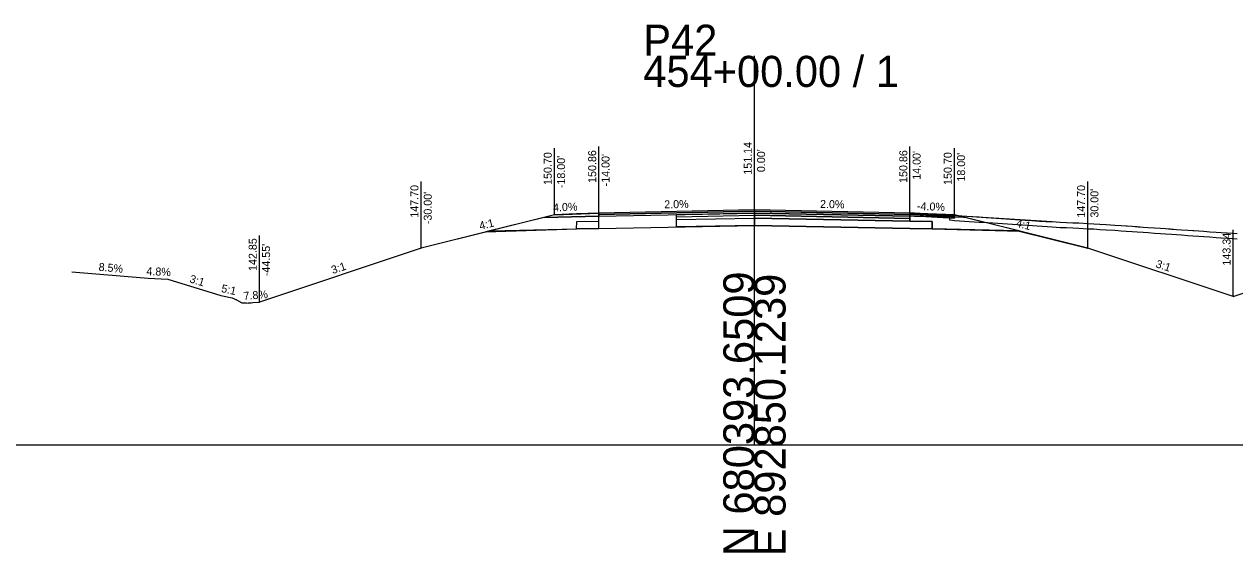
# Model space of a CAD drawing. Extents: x -26 to 4403, y -13 to 9578.
# Drawn here: x 184.3 to 293.2, y 3490.3 to 3537.8 of the extents above; entities that cross this region are included whole.
import ezdxf

# ---------------------------------------------------------------- set-up
doc = ezdxf.new("R2010")
doc.units = 0
for name, color, linetype in [('_CIVIL_CONSTRUCTION', 7, 'Continuous'), ('ASPHALT_19MM1', 7, 'Continuous'), ('ASPHALT_19MM2', 7, 'Continuous'), ('ASPHALT_9_5MM1', 7, 'Continuous'), ('CONST_DCH', 7, 'Continuous'), ('CONST_LV3', 7, 'Continuous'), ('Default', 7, 'Continuous'), ('DTM_CORRIDOR', 7, 'Continuous'), ('DTM_P_FINISHED_GRADE', 7, 'Continuous'), ('DTM_TEMP_DROP', 7, 'Continuous'), ('DTM_X_GROUND', 7, 'Continuous'), ('SLOPE_STAKES_FILL', 7, 'Continuous'), ('XS_CELL', 7, 'Continuous'), ('XS_M_EXCAVATION_LIMITS', 7, 'Continuous'), ('XS_P_ASPHALT', 7, 'Continuous'), ('XS_P_CRUSHED_STONE', 7, 'Continuous'), ('XS_P_DR_ASPHALT', 7, 'Continuous'), ('XS_P_DR_ASPHALT_B', 7, 'Continuous'), ('XS_P_DR_GRAVEL', 7, 'Continuous'), ('XS_P_GROUND', 7, 'Continuous'), ('XS_P_SHOULDER', 7, 'Continuous'), ('XS_P_SUBGRADE_GRANULAR', 7, 'Continuous'), ('XS_P_TX_CLEARZONE', 7, 'Continuous'), ('XS_P_TX_FS_BS', 7, 'Continuous')]:
    doc.layers.add(name, color=color, linetype=linetype)

msp = doc.modelspace()

# ---------------------------------------------------------------- linework, layer by layer
at = {"layer": 'ASPHALT_19MM1'}
for points in [[(243, 3520.52), (250, 3520.66), (250, 3520.66), (250, 3520.85), (250, 3520.85), (250, 3520.85)], [(250, 3520.85), (243, 3520.71)], [(250, 3520.85), (250, 3520.85), (250, 3520.85), (250, 3520.66), (250, 3520.66), (264, 3520.38), (264, 3520.57), (264, 3520.57), (250, 3520.85)]]:
    msp.add_lwpolyline(points, dxfattribs=at)
at = {"layer": 'ASPHALT_19MM2'}
msp.add_lwpolyline([(250, 3520.66), (250, 3520.66), (250, 3520.66), (250, 3520.41), (250, 3520.41), (264, 3520.13), (264, 3520.38), (264, 3520.38), (250, 3520.66)], dxfattribs=at)
at = {"layer": 'ASPHALT_9_5MM1'}
for points in [[(250, 3521.14), (236, 3520.86), (236, 3520.86), (236, 3520.74), (250, 3521.02), (250, 3521.02), (250, 3521.14), (250, 3521.14), (250, 3521.14)], [(250, 3521.14), (250, 3521.14), (250, 3521.14), (250, 3521.02), (250, 3521.02), (264, 3520.74), (264, 3520.86), (264, 3520.86), (250, 3521.14)]]:
    msp.add_lwpolyline(points, dxfattribs=at)
at = {"layer": 'CONST_LV3'}
for points in [[(264, 3520.86), (264.2, 3520.85), (264.9, 3520.83), (265.03, 3520.82), (265.2, 3520.81), (265.82, 3520.79), (266.05, 3520.78), (274.37, 3520.21), (274.96, 3520.18), (275.66, 3520.13), (276.23, 3520.11), (276.8, 3520.09), (277.53, 3520.04), (278.09, 3520.02), (278.65, 3519.99), (279.21, 3519.97), (280, 3519.92), (280.55, 3519.9), (281.1, 3519.86), (281.65, 3519.82), (282.45, 3519.78), (283, 3519.74), (283.55, 3519.7), (284, 3519.67), (284.55, 3519.63), (285, 3519.6), (285.45, 3519.57), (286, 3519.53), (286.55, 3519.49), (287, 3519.46), (287.45, 3519.43), (288, 3519.39), (288.45, 3519.36), (289, 3519.32), (289.55, 3519.28), (290, 3519.25), (290.45, 3519.22), (291, 3519.18), (291.55, 3519.14), (292, 3519.11), (292.45, 3519.08), (293, 3519.04), (293.45, 3519.01)], [(226.28, 3519.27), (220, 3517.7)], [(273.72, 3519.27), (280, 3517.7)]]:
    msp.add_lwpolyline(points, dxfattribs=at)
at = {"layer": 'Default'}
for points in [[(250, 3521.02), (236, 3520.74), (236, 3520.74), (236, 3520.57), (250, 3520.85), (250, 3520.85), (250, 3521.02), (250, 3521.02), (250, 3521.02)], [(250, 3521.02), (250, 3521.02), (250, 3521.02), (250, 3520.85), (250, 3520.85), (264, 3520.57), (264, 3520.74), (264, 3520.74), (250, 3521.02)]]:
    msp.add_lwpolyline(points, dxfattribs=at)
at = {"layer": 'DTM_P_FINISHED_GRADE'}
for points in [[(264, 3520.86), (264.41, 3520.84), (265.43, 3520.8), (268, 3520.65)], [(267.58, 3520.72), (267.58, 3520.72), (267.58, 3520.72), (267.61, 3520.71), (268, 3520.65), (270.24, 3520.51), (270.56, 3520.5), (276.8, 3520.09), (277.53, 3520.04), (278.09, 3520.02), (278.65, 3519.99), (279.21, 3519.97), (280, 3519.92), (280.55, 3519.9), (281.1, 3519.86), (281.65, 3519.82), (282.45, 3519.78), (283, 3519.74), (283.45, 3519.71), (284, 3519.67), (284.45, 3519.64), (285, 3519.6), (285.45, 3519.57), (286, 3519.53), (286.55, 3519.49), (287, 3519.46), (287.55, 3519.42), (288, 3519.39), (288.45, 3519.36), (289, 3519.32), (289.45, 3519.29), (290, 3519.25), (290.45, 3519.22), (291, 3519.18), (291.55, 3519.14), (292, 3519.11), (292.55, 3519.07), (293, 3519.04), (293.45, 3519.01)]]:
    msp.add_lwpolyline(points, dxfattribs=at)
at = {"layer": 'DTM_X_GROUND'}
msp.add_lwpolyline([(188.57, 3515.57), (195.44, 3514.99), (197.22, 3514.9), (201.99, 3513.45), (203.01, 3513.23), (203.2, 3513.14), (203.24, 3513.12), (203.29, 3513.1), (203.35, 3513.08), (203.38, 3513.06), (203.87, 3512.79), (203.91, 3512.79), (204.01, 3512.79), (204.01, 3512.79), (204.13, 3512.78), (204.28, 3512.78), (204.47, 3512.77), (204.48, 3512.78), (204.7, 3512.79), (204.86, 3512.81), (205.43, 3512.85), (205.45, 3512.85), (205.45, 3512.85)], dxfattribs=at)
at = {"layer": 'XS_CELL'}
for p, q in [((250, 3500), (250, 3535)), ((0, 3500), (250, 3500)), ((250, 3500), (400, 3500))]:
    msp.add_line(p, q, dxfattribs=at)
at = {"layer": 'XS_M_EXCAVATION_LIMITS'}
for p, q in [((236, 3519.47), (236, 3520.57)), ((243, 3519.61), (243, 3520.71))]:
    msp.add_line(p, q, dxfattribs=at)
at = {"layer": 'XS_P_ASPHALT'}
msp.add_lwpolyline([(243, 3520.27), (250, 3520.41), (250, 3520.41), (250, 3520.41), (264, 3520.13), (264, 3520.86), (264, 3520.86), (250, 3521.14), (250, 3521.14), (250, 3521.14)], dxfattribs=at)
at = {"layer": 'XS_P_CRUSHED_STONE'}
for points in [[(234, 3520.78), (232, 3520.7), (232, 3520.7), (231.07, 3520.47), (236, 3520.57), (236, 3520.57), (236, 3520.86), (236, 3520.86), (236, 3520.86), (234, 3520.78), (234, 3520.78)], [(236, 3519.47), (234, 3519.43), (234.01, 3520.09), (234.01, 3520.09), (236, 3520.13), (236, 3520.13)], [(243, 3520.27), (250, 3520.41), (250, 3520.41), (250, 3520.41), (250, 3519.75), (250, 3519.75), (243, 3519.61)], [(264, 3519.47), (266, 3519.43), (265.99, 3520.09), (265.99, 3520.09), (264, 3520.13), (264, 3520.13), (250, 3520.41), (250, 3520.41), (250, 3520.41), (250, 3519.75), (250, 3519.75), (264, 3519.47), (264, 3519.47)], [(266, 3520.78), (268, 3520.7), (268, 3520.7), (268.93, 3520.47), (264, 3520.57), (264, 3520.57), (264, 3520.86), (264, 3520.86), (264, 3520.86), (266, 3520.78), (266, 3520.78)]]:
    msp.add_lwpolyline(points, dxfattribs=at)
at = {"layer": 'XS_P_DR_ASPHALT'}
msp.add_lwpolyline([(265.43, 3520.8), (264.41, 3520.84), (264, 3520.86), (264, 3520.74), (264.41, 3520.72), (265.43, 3520.68), (268, 3520.52), (268, 3520.65), (265.43, 3520.8)], dxfattribs=at)
at = {"layer": 'XS_P_DR_ASPHALT_B'}
msp.add_lwpolyline([(265.43, 3520.68), (264.41, 3520.72), (264, 3520.74), (264, 3520.61), (264.41, 3520.59), (265.43, 3520.55), (268, 3520.4), (268, 3520.52), (265.43, 3520.68)], dxfattribs=at)
at = {"layer": 'XS_P_DR_GRAVEL'}
for points in [[(293.45, 3518.51), (293, 3518.54), (292.55, 3518.57), (292, 3518.61), (291.55, 3518.64), (291, 3518.68), (290.45, 3518.72), (290, 3518.75), (289.45, 3518.79), (289, 3518.82), (288.45, 3518.86), (288, 3518.89), (287.55, 3518.92), (287, 3518.96), (286.55, 3518.99), (286, 3519.03), (285.45, 3519.07), (285, 3519.1), (284.45, 3519.14), (284, 3519.17), (283.45, 3519.21), (283, 3519.24), (282.45, 3519.28), (281.65, 3519.32), (281.1, 3519.36), (280.55, 3519.4), (280, 3519.42), (279.21, 3519.47), (278.65, 3519.49), (278.09, 3519.52), (277.53, 3519.54), (276.8, 3519.59), (270.56, 3520), (270.24, 3520.01), (268, 3520.15), (267.61, 3520.21), (267.58, 3520.22), (267.58, 3520.22), (267.58, 3520.22), (267.58, 3520.72), (267.58, 3520.72), (267.58, 3520.72), (267.61, 3520.71), (268, 3520.65), (270.24, 3520.51)], [(270.24, 3520.51), (270.56, 3520.5), (276.8, 3520.09), (277.53, 3520.04), (278.09, 3520.02), (278.65, 3519.99), (279.21, 3519.97), (280, 3519.92), (280.55, 3519.9), (281.1, 3519.86), (281.65, 3519.82), (282.45, 3519.78), (283, 3519.74), (283.45, 3519.71), (284, 3519.67), (284.45, 3519.64), (285, 3519.6), (285.45, 3519.57), (286, 3519.53), (286.55, 3519.49), (287, 3519.46), (287.55, 3519.42), (288, 3519.39), (288.45, 3519.36), (289, 3519.32), (289.45, 3519.29), (290, 3519.25), (290.45, 3519.22), (291, 3519.18), (291.55, 3519.14), (292, 3519.11), (292.55, 3519.07), (293, 3519.04), (293.45, 3519.01)]]:
    msp.add_lwpolyline(points, dxfattribs=at)
at = {"layer": 'XS_P_GROUND'}
for points in [[(232, 3520.7), (220, 3517.7), (205.45, 3512.85)], [(293.09, 3513.34), (293.09, 3513.34), (280, 3517.7), (268, 3520.7), (268, 3520.7)], [(293.09, 3513.34), (296.91, 3514.61)]]:
    msp.add_lwpolyline(points, dxfattribs=at)
at = {"layer": 'XS_P_SHOULDER'}
for points in [[(232, 3520.7), (236, 3520.86), (236, 3520.86)], [(268, 3520.7), (264, 3520.86), (264, 3520.86)]]:
    msp.add_lwpolyline(points, dxfattribs=at)
at = {"layer": 'XS_P_SUBGRADE_GRANULAR'}
for points in [[(236, 3520.57), (236, 3520.57), (236, 3520.57), (231.07, 3520.47), (231.07, 3520.47), (225.84, 3519.16), (234, 3519.43), (234, 3519.43), (234.01, 3520.09), (234.01, 3520.09), (236, 3520.13), (236, 3520.13), (236, 3520.57)], [(264, 3520.57), (264, 3520.13), (264, 3520.13), (265.99, 3520.09), (265.99, 3520.09), (266, 3519.43), (266, 3519.43), (273.93, 3519.22), (268.93, 3520.47), (268.93, 3520.47), (264, 3520.57), (264, 3520.57), (264, 3520.57)], [(226.28, 3519.27), (234, 3519.43), (234, 3519.43), (236, 3519.47), (236, 3519.47)], [(236, 3519.47), (250, 3519.75), (250, 3519.75)], [(264, 3519.47), (250, 3519.75), (250, 3519.75)], [(273.72, 3519.27), (266, 3519.43), (266, 3519.43), (264, 3519.47), (264, 3519.47)]]:
    msp.add_lwpolyline(points, dxfattribs=at)
at = {"layer": 'XS_P_TX_CLEARZONE'}
for p, q in [((232, 3520.7), (232, 3526.7)), ((236, 3520.86), (236, 3526.86)), ((250, 3521.14), (250, 3527.14)), ((264, 3520.86), (264, 3526.86)), ((268, 3520.7), (268, 3526.7)), ((220, 3517.7), (220, 3523.7)), ((280, 3517.7), (280, 3523.7)), ((293.09, 3513.34), (293.09, 3519.34)), ((205.45, 3512.85), (205.45, 3518.85)), ((205.45, 3512.85), (205.45, 3518.85))]:
    msp.add_line(p, q, dxfattribs=at)

# ---------------------------------------------------------------- texts
at = {"layer": '_CIVIL_CONSTRUCTION'}
for p in [(249.96, 3521.08), (231.04, 3520.41), (233.96, 3520.72), (233.97, 3520.03), (235.96, 3520.8), (263.96, 3520.8), (265.96, 3520.03), (268.89, 3520.41)]:
    msp.add_text('X', height=0.12, dxfattribs=at).set_placement(p)
at = {"layer": 'CONST_DCH'}
for p in [(205.41, 3512.79), (293.05, 3513.28)]:
    msp.add_text('X', height=0.12, dxfattribs=at).set_placement(p)
at = {"layer": 'DTM_CORRIDOR'}
msp.add_text('X', height=0.12, dxfattribs=at).set_placement((205.41, 3512.79))
at = {"layer": 'DTM_TEMP_DROP'}
for p in [(231.96, 3520.64), (267.96, 3520.64)]:
    msp.add_text('X', height=0.12, dxfattribs=at).set_placement(p)
at = {"layer": 'SLOPE_STAKES_FILL'}
for p in [(219.96, 3517.64), (279.96, 3517.64)]:
    msp.add_text('X', height=0.12, dxfattribs=at).set_placement(p)
at = {"layer": 'XS_CELL'}
for s, p in [('P42', (240, 3535)), ('454+00.00 / 1', (240, 3532.2))]:
    msp.add_text(s, height=2.8, dxfattribs=at).set_placement(p)
for s, p in [('N 680393.6509', (250, 3490)), ('E 892850.1239', (252.8, 3490))]:
    msp.add_text(s, height=2.8, rotation=90, dxfattribs=at).set_placement(p)
at = {"layer": 'XS_P_TX_CLEARZONE'}
for s, p in [('151.14', (249.76, 3524.31)), ('150.70', (231.76, 3523.39)), ("-18.00'", (232.96, 3523.1)), ('150.86', (235.76, 3523.57)), ("-14.00'", (236.96, 3523.26)), ("0.00'", (250.96, 3524.54)), ('150.86', (263.76, 3523.57)), ("14.00'", (264.96, 3523.85)), ('150.70', (267.76, 3523.39)), ("18.00'", (268.96, 3523.69)), ('147.70', (219.76, 3520.44)), ("-30.00'", (220.96, 3519.86)), ('147.70', (279.76, 3520.44)), ("30.00'", (280.96, 3520.45)), ('143.34', (292.85, 3516.14)), ('142.85', (205.21, 3515.65)), ('142.85', (205.21, 3515.65)), ("-44.55'", (206.41, 3515.18)), ("-44.55'", (206.41, 3515.18))]:
    msp.add_text(s, height=0.72, rotation=90, dxfattribs=at).set_placement(p)
at = {"layer": 'XS_P_TX_FS_BS'}
for s, rotation, p in [('4.0%', 2.2906, (231.89, 3521)), ('2.0%', 1.1458, (241.89, 3521.28)), ('2.0%', 358.8542, (255.9, 3521.32)), ('-4.0%', 357.7094, (264.62, 3521.14)), ('-4.0%', 357.7094, (264.62, 3521.14)), ('4:1', 14.0362, (225.33, 3519.34)), ('4:1', 345.9638, (273.48, 3519.64)), ('8.5%', 355.1636, (190.96, 3515.67)), ('8.5%', 355.1636, (190.96, 3515.67)), ('4.8%', 357.2543, (195.27, 3515.29)), ('4.8%', 357.2543, (195.27, 3515.29)), ('3:1', 18.4332, (212.05, 3515.37)), ('3:1', 341.5668, (286.06, 3516)), ('3:1', 343.0958, (199.11, 3514.64)), ('3:1', 343.0958, (199.11, 3514.64)), ('5:1', 347.6657, (201.97, 3513.76)), ('5:1', 347.6657, (201.97, 3513.76)), ('7.8%', 4.4614, (204.05, 3513.04)), ('7.8%', 4.4614, (204.05, 3513.04))]:
    msp.add_text(s, height=0.72, rotation=rotation, dxfattribs=at).set_placement(p)

doc.saveas('drawing.dxf')
